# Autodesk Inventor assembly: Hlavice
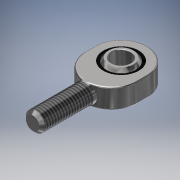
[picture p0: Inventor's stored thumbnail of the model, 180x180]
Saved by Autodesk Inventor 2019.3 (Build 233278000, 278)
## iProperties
Created: 2019-01
Part Number: Hlavice
Material: Všeobecné
Document SubType Name: Assembly
Designer: B-hon
Mass: 125.717 g
Surface Area: 69.0449 cm^2
Volume: 16.0655 cm^3
Density: 7.8253 g/cm^3
Author: B-hon
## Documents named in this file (3)
- C:\Users\B-hon\OneDrive\Plocha\Bakalářka\Ojnice\Hlavice.iam
- C:\Users\B-hon\OneDrive\Plocha\Bakalářka\Ojnice\Hlavice.ipt
- C:\Users\B-hon\OneDrive\Plocha\Bakalářka\Ojnice\Vnitřní kroužek.ipt
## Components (2 placed, 2 different names)
1. Hlavice:1 — Proti sobě:1, Úhel:1
2. Vnitřní kroužek:1 — Proti sobě:1, Úhel:1
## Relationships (2: Mate 1, Angle 1)
- Proti sobě:1 [Mate]: Hlavice:1 ↔ Vnitřní kroužek:1
- Úhel:1 [Angle]: Hlavice:1 ↔ Vnitřní kroužek:1
